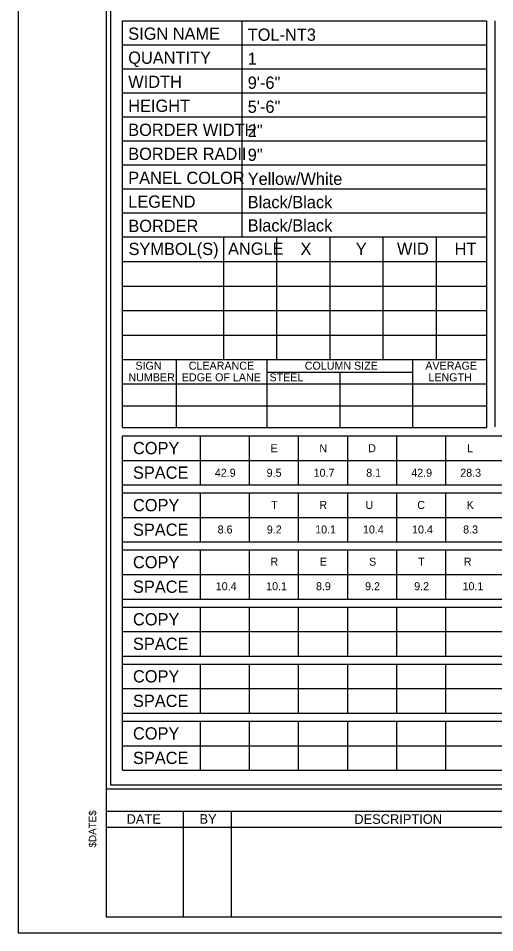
# Model space of a CAD drawing. Extents: x 17890628 to 17890844, y 17897508 to 17897992.
# Drawn here: x 17890700.47 to 17890726.43, y 17897507.74 to 17897557.55 of the extents above; entities that cross this region are included whole.
import ezdxf

# ---------------------------------------------------------------- set-up
doc = ezdxf.new("R2010")
doc.units = 0
for name, color, linetype in [('GSSign', 7, 'Continuous'), ('PlotBorder_dp', 7, 'Continuous'), ('SheetBorder_dp', 7, 'Continuous'), ('SheetLinesMisc2_dp', 7, 'Continuous'), ('TextMinor', 7, 'Continuous'), ('TextMisc', 7, 'Continuous')]:
    doc.layers.add(name, color=color, linetype=linetype)

msp = doc.modelspace()

# ---------------------------------------------------------------- linework, layer by layer
at = {"layer": 'PlotBorder_dp'}
msp.add_lwpolyline([(17890700.471, 17897507.741), (17890844.259, 17897507.741), (17890844.259, 17897600.116), (17890700.471, 17897600.116)], close=True, dxfattribs=at)
at = {"layer": 'SheetBorder_dp'}
for p, q in [((17890705.263, 17897599.245), (17890705.263, 17897508.613)), ((17890705.263, 17897515.585), (17890839.466, 17897515.585)), ((17890705.263, 17897514.365), (17890755.459, 17897514.365)), ((17890709.446, 17897514.365), (17890709.446, 17897508.613)), ((17890712.061, 17897514.365), (17890712.061, 17897508.613)), ((17890705.263, 17897513.493), (17890755.459, 17897513.493)), ((17890705.263, 17897508.613), (17890839.466, 17897508.613))]:
    msp.add_line(p, q, dxfattribs=at)
at = {"layer": 'SheetLinesMisc2_dp'}
for p, q in [((17890705.5, 17897599.039), (17890705.5, 17897515.791)), ((17890706.142, 17897535.259), (17890706.142, 17897557.415)), ((17890706.142, 17897557.415), (17890725.973, 17897557.415)), ((17890712.643, 17897557.415), (17890712.643, 17897556.106)), ((17890725.973, 17897557.415), (17890725.973, 17897535.259)), ((17890726.429, 17897557.416), (17890726.429, 17897535.291)), ((17890706.142, 17897556.106), (17890725.973, 17897556.106)), ((17890712.643, 17897556.106), (17890712.643, 17897545.634)), ((17890706.142, 17897554.797), (17890725.973, 17897554.797)), ((17890706.142, 17897553.489), (17890725.973, 17897553.489)), ((17890706.142, 17897552.18), (17890725.973, 17897552.18)), ((17890706.142, 17897550.871), (17890725.973, 17897550.871)), ((17890706.142, 17897549.563), (17890725.973, 17897549.563)), ((17890706.142, 17897548.254), (17890716.057, 17897548.254)), ((17890716.057, 17897548.254), (17890725.973, 17897548.254)), ((17890706.142, 17897546.946), (17890716.057, 17897546.946)), ((17890716.057, 17897546.946), (17890725.973, 17897546.946)), ((17890706.141, 17897545.634), (17890725.973, 17897545.634)), ((17890711.644, 17897545.634), (17890711.644, 17897538.953)), ((17890714.542, 17897545.634), (17890714.542, 17897538.953)), ((17890717.44, 17897545.634), (17890717.44, 17897538.953)), ((17890720.337, 17897545.634), (17890720.337, 17897538.953)), ((17890723.235, 17897545.634), (17890723.235, 17897538.953)), ((17890706.141, 17897544.298), (17890725.973, 17897544.298)), ((17890706.141, 17897542.961), (17890725.973, 17897542.961)), ((17890706.141, 17897541.625), (17890725.973, 17897541.625)), ((17890706.141, 17897540.289), (17890725.973, 17897540.289)), ((17890706.141, 17897538.953), (17890725.973, 17897538.953)), ((17890709.08, 17897538.953), (17890709.08, 17897535.26)), ((17890714.015, 17897538.953), (17890714.015, 17897535.26)), ((17890721.947, 17897538.953), (17890721.947, 17897535.26)), ((17890714.015, 17897538.272), (17890721.947, 17897538.272)), ((17890717.981, 17897538.272), (17890717.981, 17897535.26)), ((17890706.141, 17897537.633), (17890725.973, 17897537.633)), ((17890706.141, 17897536.446), (17890725.973, 17897536.446)), ((17890706.142, 17897535.259), (17890725.973, 17897535.259)), ((17890706.142, 17897534.804), (17890771.912, 17897534.804)), ((17890706.142, 17897516.593), (17890706.142, 17897534.804)), ((17890710.375, 17897534.804), (17890710.375, 17897532.131)), ((17890713.051, 17897534.804), (17890713.051, 17897532.131)), ((17890715.727, 17897534.804), (17890715.727, 17897532.131)), ((17890718.402, 17897534.804), (17890718.402, 17897532.131)), ((17890721.077, 17897534.804), (17890721.077, 17897532.131)), ((17890723.753, 17897534.804), (17890723.753, 17897532.131)), ((17890706.142, 17897533.468), (17890771.912, 17897533.468)), ((17890706.142, 17897532.131), (17890771.912, 17897532.131)), ((17890706.142, 17897531.696), (17890771.912, 17897531.696)), ((17890710.375, 17897531.696), (17890710.375, 17897529.023)), ((17890713.051, 17897531.696), (17890713.051, 17897529.023)), ((17890715.727, 17897531.696), (17890715.727, 17897529.023)), ((17890718.402, 17897531.696), (17890718.402, 17897529.023)), ((17890721.077, 17897531.696), (17890721.077, 17897529.023)), ((17890723.753, 17897531.696), (17890723.753, 17897529.023)), ((17890706.142, 17897530.359), (17890771.912, 17897530.359)), ((17890706.142, 17897529.023), (17890771.912, 17897529.023)), ((17890706.142, 17897528.588), (17890771.912, 17897528.588)), ((17890710.375, 17897528.588), (17890710.375, 17897525.916)), ((17890713.051, 17897528.588), (17890713.051, 17897525.916)), ((17890715.727, 17897528.588), (17890715.727, 17897525.916)), ((17890718.402, 17897528.588), (17890718.402, 17897525.916)), ((17890721.077, 17897528.588), (17890721.077, 17897525.916)), ((17890723.753, 17897528.588), (17890723.753, 17897525.916)), ((17890706.142, 17897527.252), (17890771.912, 17897527.252)), ((17890706.142, 17897525.916), (17890771.912, 17897525.916)), ((17890706.142, 17897525.48), (17890771.912, 17897525.48)), ((17890710.375, 17897525.48), (17890710.375, 17897522.808)), ((17890713.051, 17897525.48), (17890713.051, 17897522.808)), ((17890715.727, 17897525.48), (17890715.727, 17897522.808)), ((17890718.402, 17897525.48), (17890718.402, 17897522.808)), ((17890721.077, 17897525.48), (17890721.077, 17897522.808)), ((17890723.753, 17897525.48), (17890723.753, 17897522.808)), ((17890706.142, 17897524.145), (17890771.912, 17897524.145)), ((17890706.142, 17897522.808), (17890771.912, 17897522.808)), ((17890706.142, 17897522.372), (17890771.912, 17897522.372)), ((17890710.375, 17897522.372), (17890710.375, 17897519.7)), ((17890713.051, 17897522.372), (17890713.051, 17897519.7)), ((17890715.727, 17897522.372), (17890715.727, 17897519.7)), ((17890718.402, 17897522.372), (17890718.402, 17897519.7)), ((17890721.077, 17897522.372), (17890721.077, 17897519.7)), ((17890723.753, 17897522.372), (17890723.753, 17897519.7)), ((17890706.142, 17897521.036), (17890771.912, 17897521.036)), ((17890706.142, 17897519.7), (17890771.912, 17897519.7)), ((17890706.142, 17897519.264), (17890771.912, 17897519.264)), ((17890710.375, 17897519.264), (17890710.375, 17897516.593)), ((17890713.051, 17897519.264), (17890713.051, 17897516.593)), ((17890715.727, 17897519.264), (17890715.727, 17897516.593)), ((17890718.402, 17897519.264), (17890718.402, 17897516.593)), ((17890721.077, 17897519.264), (17890721.077, 17897516.593)), ((17890723.753, 17897519.264), (17890723.753, 17897516.593)), ((17890706.142, 17897517.928), (17890771.912, 17897517.928)), ((17890706.142, 17897516.593), (17890771.912, 17897516.593)), ((17890705.5, 17897515.791), (17890839.233, 17897515.791))]:
    msp.add_line(p, q, dxfattribs=at)

# ---------------------------------------------------------------- texts
at = {"layer": 'GSSign'}
for s, height, p in [('TOL-NT3', 0.6667, (17890712.971, 17897556.321)), ('1', 0.667, (17890712.971, 17897555.013)), ('9\'-6"', 0.6667, (17890712.971, 17897553.704)), ('5\'-6"', 0.6667, (17890712.971, 17897552.396)), ('2"', 0.6667, (17890712.971, 17897551.087)), ('9"', 0.6667, (17890712.971, 17897549.778)), ('Yellow/White', 0.66667, (17890712.971, 17897548.47)), ('Black/Black', 0.66667, (17890712.971, 17897547.201)), ('Black/Black', 0.66667, (17890712.971, 17897545.932)), ('E', 0.436, (17890714.215, 17897533.911)), ('N', 0.436, (17890716.873, 17897533.911)), ('D', 0.436, (17890719.534, 17897533.911)), ('L', 0.436, (17890724.93, 17897533.911)), ('42.9', 0.4357, (17890711.18, 17897532.575)), ('9.5', 0.4357, (17890714.002, 17897532.575)), ('10.7', 0.4357, (17890716.564, 17897532.575)), ('8.1', 0.4357, (17890719.429, 17897532.575)), ('42.9', 0.4357, (17890721.882, 17897532.575)), ('28.3', 0.4357, (17890724.552, 17897532.575)), ('T', 0.436, (17890714.25, 17897530.822)), ('R', 0.436, (17890716.875, 17897530.822)), ('U', 0.436, (17890719.386, 17897530.822)), ('C', 0.436, (17890722.209, 17897530.822)), ('K', 0.436, (17890724.899, 17897530.822)), ('8.6', 0.4357, (17890711.334, 17897529.485)), ('9.2', 0.4357, (17890714.012, 17897529.485)), ('10.1', 0.4357, (17890716.647, 17897529.485)), ('10.4', 0.4357, (17890719.249, 17897529.485)), ('10.4', 0.4357, (17890721.924, 17897529.485)), ('8.3', 0.4357, (17890724.708, 17897529.485)), ('R', 0.436, (17890714.212, 17897527.732)), ('E', 0.436, (17890716.898, 17897527.732)), ('S', 0.436, (17890719.584, 17897527.732)), ('T', 0.436, (17890722.26, 17897527.732)), ('R', 0.436, (17890724.745, 17897527.732)), ('10.4', 0.4357, (17890711.228, 17897526.396)), ('10.1', 0.4357, (17890713.975, 17897526.396)), ('8.9', 0.4357, (17890716.691, 17897526.396)), ('9.2', 0.4357, (17890719.366, 17897526.396)), ('9.2', 0.4357, (17890722.042, 17897526.396)), ('10.1', 0.4357, (17890724.677, 17897526.396))]:
    msp.add_text(s, height=height, dxfattribs=at).set_placement(p)
at = {"layer": 'TextMinor'}
for s, height, p in [('SIGN NAME', 0.6667, (17890706.461, 17897556.375)), ('QUANTITY', 0.6667, (17890706.461, 17897555.066)), ('WIDTH', 0.6667, (17890706.461, 17897553.757)), ('HEIGHT', 0.6667, (17890706.461, 17897552.449)), ('BORDER WIDTH', 0.66667, (17890706.461, 17897551.14)), ('BORDER RADII', 0.66667, (17890706.461, 17897549.831)), ('PANEL COLOR', 0.66667, (17890706.461, 17897548.523)), ('LEGEND', 0.6667, (17890706.461, 17897547.226)), ('BORDER', 0.6667, (17890706.467, 17897545.906)), ('SYMBOL(S)', 0.6667, (17890706.478, 17897544.651)), ('ANGLE', 0.6667, (17890711.899, 17897544.665)), ('X', 0.667, (17890715.846, 17897544.651)), ('Y', 0.667, (17890718.859, 17897544.651)), ('WID', 0.6667, (17890721.103, 17897544.665)), ('HT', 0.6667, (17890724.244, 17897544.653)), ('SIGN', 0.4357, (17890706.852, 17897538.408)), ('CLEARANCE', 0.4357, (17890709.759, 17897538.407)), ('COLUMN SIZE', 0.43573, (17890716.077, 17897538.407)), ('AVERAGE', 0.4357, (17890722.648, 17897538.407)), ('NUMBER', 0.4357, (17890706.473, 17897537.774)), ('EDGE OF LANE', 0.43573, (17890709.38, 17897537.774)), ('STEEL    ', 0.4357, (17890714.156, 17897537.774)), ('LENGTH', 0.4357, (17890722.817, 17897537.774)), ('COPY', 0.6667, (17890706.719, 17897533.805)), ('SPACE', 0.6667, (17890706.719, 17897532.468)), ('COPY', 0.6667, (17890706.719, 17897530.696)), ('SPACE', 0.6667, (17890706.719, 17897529.36)), ('COPY', 0.6667, (17890706.719, 17897527.589)), ('SPACE', 0.6667, (17890706.719, 17897526.253)), ('COPY', 0.6667, (17890706.719, 17897524.48)), ('SPACE', 0.6667, (17890706.719, 17897523.145)), ('COPY', 0.6667, (17890706.719, 17897521.372)), ('SPACE', 0.6667, (17890706.719, 17897520.036)), ('COPY', 0.6667, (17890706.719, 17897518.264)), ('SPACE', 0.6667, (17890706.719, 17897516.929))]:
    msp.add_text(s, height=height, dxfattribs=at).set_placement(p)
msp.add_text('$DATE$', height=0.4008, rotation=90, dxfattribs=at).set_placement((17890704.715, 17897512.382))
at = {"layer": 'TextMisc'}
for s, height, rotation, p in [('DATE', 0.5229, 359.8693, (17890706.371, 17897513.675)), ('DESCRIPTION', 0.52276, 0.0498, (17890718.78, 17897513.666))]:
    msp.add_text(s, height=height, rotation=rotation, dxfattribs=at).set_placement(p)
msp.add_text('BY', height=0.5229, dxfattribs=at).set_placement((17890710.345, 17897513.675))

doc.saveas('drawing.dxf')
